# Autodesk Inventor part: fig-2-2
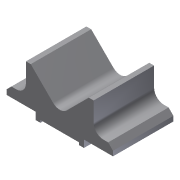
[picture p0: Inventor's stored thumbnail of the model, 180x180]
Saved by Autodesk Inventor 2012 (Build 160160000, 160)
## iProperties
Shininess: 64.0
Length Units: 11269
Angle Units: 11279
Time Units: 11290
Mass Units: 11283
Length Display Precision: 3
Angle Display Precision: 2
Compacted: True
Part Number: fig-2-2
Document SubType Name: Modeling
Created: 2002-11
Designer: deepak
Density: 1 g/cm^3
Material: Default
Density: 0.0
Volumn: 0.0
Area: 0.0
PropertySet Name: Model Information
Control State: 0
Master: False
Checked Out: False
Author: CADCIM
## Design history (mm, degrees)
sketch "Sketch1"
  geometry: L1 (0, 0)-(-3, 3); L2 (-3, 3)-(-3.5, 3); L3 (-3.5, 3)-(-3.5, 0); L4 (-3.5, 0)-(-5.5, 0); L5 (-5.5, 0)-(-5.5, -1); L6 (-5.5, -1)-(-2.5, -1); L7 (-2.5, -1)-(-2.5, -1.75); L8 (-2.5, -1.75)-(-2, -1.75); L9 (-2, -1.75)-(-2, -1.5); L10 (-2, -1.5)-(2, -1.5); L11 (2, -1.5)-(2, -1.75); L12 (2, -1.75)-(2.5, -1.75); L13 (2.5, -1.75)-(2.5, -1); L14 (2.5, -1)-(5.5, -1); L15 (5.5, -1)-(5.5, 0); L16 (5.5, 0)-(3.5, 0); L17 (3.5, 0)-(3.5, 3); L18 (3.5, 3)-(3, 3); L19 (3, 3)-(0, 0)
  constraints: 38 end point, 17 perpendicular, 1 horizontal
extrude "Extrusion1" new body sketch "Sketch1" distance "d0" = 6.25; taper "d1" = 0 deg
fillet "Fillet1" dims "d2" = 1
chamfer "Chamfer1" distance "d3" = 0.5; stored, may be unused: second distance "d4" = 2, angle "d5" = 45 deg
body "Solid1"
